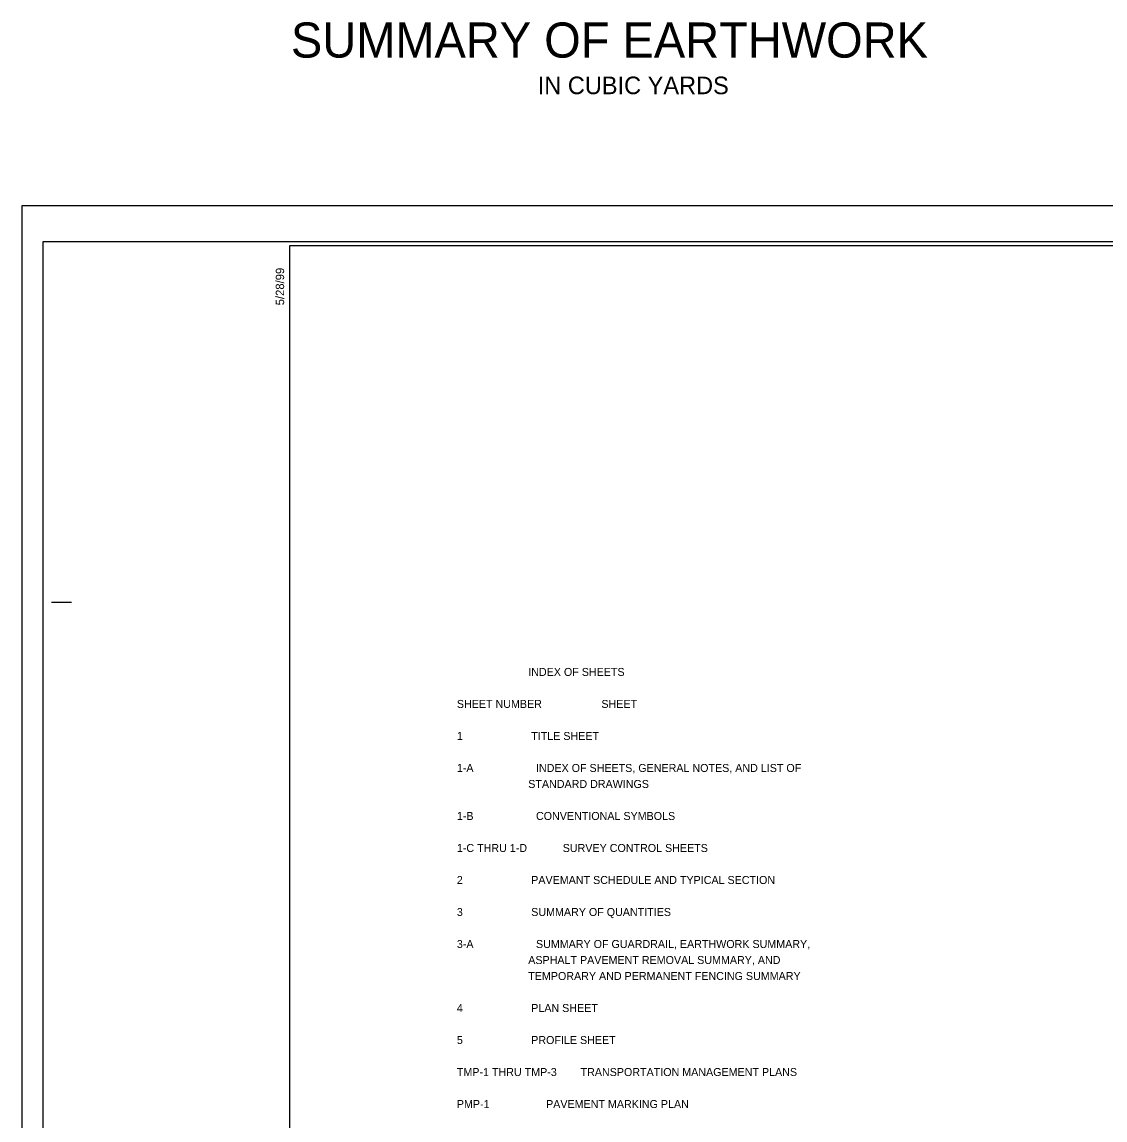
# Model space of a CAD drawing. Extents: x 1728265 to 1732106, y 539919 to 543766.
# Drawn here: x 1729453 to 1730130, y 543079 to 543766 of the extents above; entities that cross this region are included whole.
import ezdxf

# ---------------------------------------------------------------- set-up
doc = ezdxf.new("R2010")
doc.units = 0
for name, color, linetype in [('Default', 7, 'Continuous'), ('Sheet Cutting Line CELL', 7, 'Continuous'), ('Sheet Plot Border Inside CELL', 7, 'Continuous'), ('Sheet Plot Border Outside CELL', 7, 'Continuous'), ('Sheet Summary CELL', 7, 'Continuous')]:
    doc.layers.add(name, color=color, linetype=linetype)

msp = doc.modelspace()

# ---------------------------------------------------------------- linework, layer by layer
at = {"layer": 'Sheet Cutting Line CELL'}
for p, q in [((1731137.34, 543650.62), (1729453.34, 543650.62)), ((1729453.34, 543650.62), (1729453.34, 542550.62))]:
    msp.add_line(p, q, dxfattribs=at)
at = {"layer": 'Sheet Plot Border Inside CELL'}
msp.add_lwpolyline([(1731132.84, 543628.17), (1729466.34, 543628.17), (1729466.34, 542573.07), (1731132.84, 542573.07)], close=True, dxfattribs=at)
at = {"layer": 'Sheet Plot Border Outside CELL'}
msp.add_lwpolyline([(1731137.34, 543650.62), (1729453.34, 543650.62), (1729453.34, 542550.62), (1731137.34, 542550.62)], close=True, dxfattribs=at)
at = {"layer": 'Sheet Summary CELL'}
for p, q in [((1729620.34, 543625.62), (1729620.34, 543585.17)), ((1729471.84, 543403.12), (1729484.34, 543403.12))]:
    msp.add_line(p, q, dxfattribs=at)
msp.add_lwpolyline([(1731120.34, 543625.62), (1729620.34, 543625.62), (1729620.34, 542575.62), (1731120.34, 542575.62)], close=True, dxfattribs=at)

# ---------------------------------------------------------------- texts
at = {"layer": 'Default'}
for s, p in [('                        INDEX OF SHEETS ', (1729724.98, 543356.93)), ('SHEET NUMBER                    SHEET   ', (1729724.98, 543336.93)), ('1                       TITLE SHEET', (1729724.98, 543316.93)), ('1-A                     INDEX OF SHEETS, GENERAL NOTES, AND LIST OF ', (1729724.98, 543296.93)), ('                        STANDARD DRAWINGS', (1729724.98, 543286.93)), ('1-B                     CONVENTIONAL SYMBOLS ', (1729724.98, 543266.93)), ('1-C THRU 1-D            SURVEY CONTROL SHEETS', (1729724.98, 543246.93)), ('2                       PAVEMANT SCHEDULE AND TYPICAL SECTION', (1729724.98, 543226.93)), ('3                       SUMMARY OF QUANTITIES ', (1729724.98, 543206.93)), ('3-A                     SUMMARY OF GUARDRAIL, EARTHWORK SUMMARY,', (1729724.98, 543186.93)), ('                        ASPHALT PAVEMENT REMOVAL SUMMARY, AND ', (1729724.98, 543176.93)), ('                        TEMPORARY AND PERMANENT FENCING SUMMARY', (1729724.98, 543166.93)), ('4                       PLAN SHEET', (1729724.98, 543146.93)), ('5                       PROFILE SHEET', (1729724.98, 543126.93)), ('TMP-1 THRU TMP-3        TRANSPORTATION MANAGEMENT PLANS', (1729724.98, 543106.93)), ('PMP-1                   PAVEMENT MARKING PLAN', (1729724.98, 543086.93))]:
    msp.add_text(s, height=5, dxfattribs=at).set_placement(p)
at = {"layer": 'Sheet Summary CELL'}
for s, height, p in [('SUMMARY OF EARTHWORK', 21.9501, (1729621.34, 543743.28)), ('IN CUBIC YARDS', 10.9998, (1729775.49, 543720.43))]:
    msp.add_text(s, height=height, dxfattribs=at).set_placement(p)
msp.add_text('5/28/99', height=5.25, rotation=90, dxfattribs=at).set_placement((1729617.09, 543588.52))

doc.saveas('drawing.dxf')
